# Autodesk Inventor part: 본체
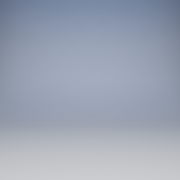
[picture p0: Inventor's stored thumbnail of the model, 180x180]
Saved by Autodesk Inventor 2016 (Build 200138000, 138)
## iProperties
Created: 2018-07
Part Number: 본체
Material: Generic
Document SubType Name: Modeling
Designer: 2-PC11
Density: 1 g/cm^3
Appearance: Default
Author: 2-PC11
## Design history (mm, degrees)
